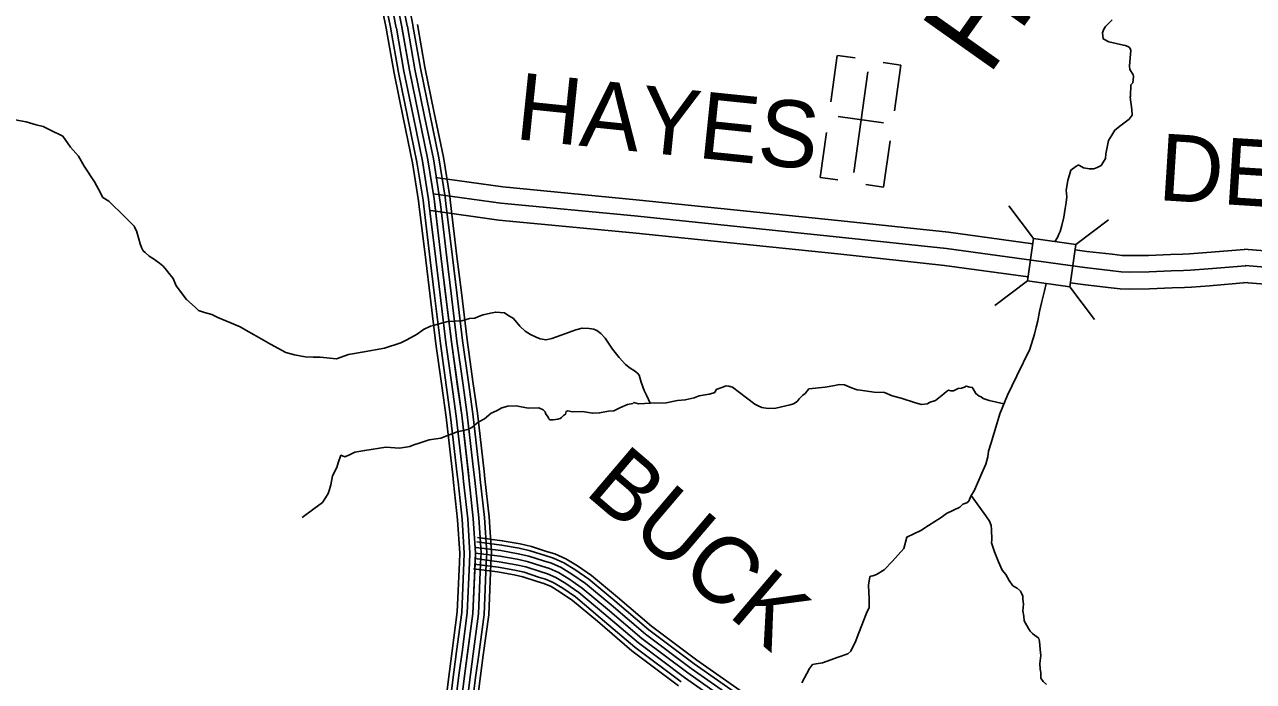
# Model space of a CAD drawing. Extents: x 1551132 to 1791609, y 378168 to 563823.
# Drawn here: x 1664184 to 1670994, y 434729 to 438369 of the extents above; entities that cross this region are included whole.
import ezdxf

# ---------------------------------------------------------------- set-up
doc = ezdxf.new("R2010")
doc.units = 0
for name, color, linetype in [('DESIGN - DRAINAGE - Bridges and Cross Drains Size Text', 7, 'Continuous'), ('DESIGN - ROW - Right-of-Way and Easement Labels', 7, 'Continuous'), ('DESIGN - TRANSPORTATION - Text', 7, 'Continuous'), ('DESIGN - UTILITIES - Cable (Underground) with Text', 7, 'Continuous'), ('SURVEY - CONTOURS - Index with Text', 7, 'Continuous'), ('SURVEY - DRAINAGE - Storm Sewer', 7, 'Continuous'), ('SURVEY - PROPERTY - Owners', 7, 'Continuous'), ('SURVEY - TRANSPORTATION - Roads', 7, 'Continuous')]:
    doc.layers.add(name, color=color, linetype=linetype)

msp = doc.modelspace()

# ---------------------------------------------------------------- linework, layer by layer
at = {"layer": 'DESIGN - TRANSPORTATION - Text'}
for points in [[(1670210.384, 438395.73), (1670174.051, 438357.996), (1670163.893, 438340.054), (1670157.743, 438324.087), (1670161.427, 438289.994), (1670193.259, 438273.677), (1670273.049, 438254.927), (1670285.024, 438252.818), (1670304.94, 438244.618), (1670310.865, 438236.551), (1670314.773, 438226.501), (1670310.381, 438184.475), (1670307.956, 438138.415), (1670309.79, 438120.373), (1670325.539, 438094.181), (1670327.514, 438092.164), (1670329.406, 438080.122), (1670325.089, 438046.113), (1670315.006, 438036.188), (1670312.406, 437972.103), (1670310.356, 437966.111), (1670319.714, 437897.909), (1670321.439, 437867.85), (1670305.24, 437845.958), (1670260.949, 437812.307), (1670226.708, 437784.564), (1670208.458, 437756.689), (1670190.184, 437726.805), (1670175.509, 437652.811), (1670173.268, 437626.794), (1670159.051, 437602.876), (1670150.926, 437588.926), (1670128.827, 437577.109), (1670108.761, 437569.275), (1670084.77, 437569.5), (1670052.845, 437575.801), (1670030.971, 437588.018), (1670026.988, 437590.051), (1670022.988, 437590.093), (1670008.921, 437582.209), (1669982.755, 437562.409), (1669966.222, 437504.465), (1669955.748, 437452.472), (1669959.389, 437414.38), (1669957.089, 437382.345), (1669950.798, 437350.345), (1669942.356, 437302.343), (1669931.931, 437256.367), (1669923.623, 437222.383), (1669915.498, 437208.433), (1669907.315, 437188.474), (1669895.141, 437168.548), (1669894.607, 437167.765)], [(1664111.743, 437845.746), (1664191.558, 437831.171), (1664247.373, 437812.762), (1664287.272, 437804.47), (1664327.08, 437784.17), (1664394.778, 437751.652), (1664438.277, 437689.259), (1664481.876, 437640.883), (1664513.434, 437584.59), (1664570.749, 437498.062), (1664592.432, 437457.853), (1664618.064, 437411.61), (1664649.889, 437391.36), (1664739.162, 437304.616), (1664778.827, 437264.281), (1664790.727, 437252.181), (1664792.702, 437248.164), (1664800.577, 437232.089), (1664804.527, 437226.047), (1664814.235, 437187.929), (1664823.976, 437153.812), (1664831.826, 437133.728), (1664841.684, 437115.636), (1664851.6, 437105.552), (1664873.433, 437085.368), (1664897.299, 437071.185), (1664931.09, 437046.917), (1664948.973, 437032.767), (1664962.839, 437016.65), (1664990.564, 436982.407), (1665006.397, 436962.274), (1665024.088, 436922.089), (1665081.47, 436845.579), (1665129.11, 436803.194), (1665146.96, 436785.044), (1665180.843, 436772.785), (1665220.725, 436762.493), (1665254.574, 436746.235), (1665320.298, 436717.742), (1665378.063, 436693.308), (1665409.895, 436675.058), (1665455.669, 436650.707), (1665547.192, 436597.998), (1665630.774, 436551.346), (1665678.631, 436538.996), (1665738.496, 436528.563), (1665782.437, 436526.254), (1665822.394, 436525.979), (1665912.242, 436517.346), (1665978.349, 436540.921), (1666054.372, 436554.413), (1666178.402, 436575.581), (1666268.525, 436604.998), (1666302.624, 436622.79), (1666358.798, 436654.441), (1666394.947, 436680.225)], [(1669844.442, 436934.05), (1669836.617, 436894.624), (1669820, 436826.664), (1669807.559, 436778.696), (1669799.076, 436726.687), (1669790.768, 436692.711), (1669780.401, 436652.735), (1669755.652, 436570.824), (1669682.312, 436423.245), (1669631.338, 436315.526), (1669588.389, 436211.748), (1669540.932, 436051.91), (1669526.507, 436005.968), (1669522.215, 435973.95), (1669511.849, 435933.982), (1669489.399, 435884.098), (1669448.525, 435788.312), (1669428.234, 435756.444), (1669415.984, 435728.51), (1669405.893, 435718.585), (1669383.835, 435710.768), (1669367.694, 435694.893), (1669293.396, 435659.508)], [(1666394.947, 436680.225), (1666433.046, 436697.992), (1666449.054, 436701.884), (1666473.087, 436709.726), (1666529.136, 436723.36), (1666607.076, 436726.827), (1666649.141, 436740.552), (1666679.124, 436742.344), (1666699.174, 436752.219), (1666725.206, 436760.053), (1666765.239, 436769.786), (1666795.246, 436775.586), (1666843.17, 436771.245), (1666861.061, 436759.103), (1666892.894, 436740.86), (1666928.552, 436698.551), (1666958.317, 436670.3), (1666988.15, 436652.066), (1667018.016, 436637.841), (1667041.924, 436627.666), (1667073.848, 436621.432), (1667105.872, 436629.224), (1667157.963, 436648.883), (1667238.094, 436678.376), (1667274.118, 436686.134), (1667312.076, 436685.868), (1667338.017, 436681.684), (1667355.941, 436673.551), (1667377.799, 436657.375), (1667401.59, 436631.174), (1667441.106, 436570.806), (1667478.73, 436524.48), (1667514.413, 436486.179), (1667540.245, 436465.97), (1667564.103, 436449.786), (1667579.994, 436437.653), (1667589.894, 436425.569), (1667601.611, 436387.435), (1667617.252, 436341.259), (1667631.052, 436315.125), (1667650.593, 436270.79)], [(1669611.305, 436267.124), (1669528.94, 436285.908), (1669497.049, 436296.142), (1669485.133, 436306.242), (1669473.175, 436310.334), (1669455.3, 436324.476), (1669441.501, 436350.61), (1669435.568, 436358.66), (1669421.593, 436360.76), (1669401.643, 436364.91), (1669393.61, 436358.952), (1669375.602, 436355.077), (1669357.603, 436353.193), (1669331.528, 436339.36), (1669317.545, 436339.451), (1669303.587, 436343.56), (1669293.538, 436335.618), (1669277.471, 436323.709), (1669231.239, 436285.975), (1669203.198, 436276.158), (1669185.157, 436268.274), (1669155.157, 436264.474), (1669121.25, 436272.724), (1669041.527, 436299.308), (1668991.67, 436311.675), (1668949.846, 436329.992), (1668891.922, 436332.401), (1668814.074, 436342.951), (1668798.108, 436345.068), (1668766.208, 436355.301), (1668728.384, 436373.593), (1668698.41, 436373.802), (1668674.41, 436369.96), (1668620.395, 436360.326), (1668530.414, 436350.934), (1668510.248, 436325.034), (1668496.19, 436315.117), (1668476.065, 436295.233), (1668465.974, 436281.283), (1668445.891, 436267.399), (1668425.866, 436261.532), (1668347.818, 436244.048), (1668303.844, 436242.348), (1668269.912, 436246.59), (1668250.004, 436256.748), (1668230.087, 436264.89), (1668184.397, 436301.266), (1668106.899, 436359.884), (1668086.966, 436366.035), (1668071, 436368.143), (1668046.95, 436358.301), (1668016.892, 436346.492), (1668008.784, 436330.525), (1667998.768, 436326.592), (1667976.743, 436320.733), (1667922.728, 436311.091), (1667894.687, 436301.274), (1667844.647, 436289.607), (1667802.664, 436285.891), (1667738.632, 436272.315), (1667652.709, 436270.907), (1667586.744, 436267.365), (1667560.828, 436275.557), (1667554.795, 436269.59), (1667524.779, 436263.79), (1667482.697, 436246.056), (1667448.597, 436228.264), (1667420.615, 436226.456), (1667370.591, 436216.789), (1667330.617, 436215.064), (1667274.751, 436225.472), (1667220.794, 436223.839), (1667194.845, 436228.03), (1667184.829, 436224.089), (1667180.729, 436210.097), (1667170.687, 436202.155), (1667158.621, 436192.23), (1667152.588, 436186.263), (1667138.571, 436182.354), (1667112.572, 436178.529), (1667094.589, 436178.654), (1667088.639, 436184.704), (1667082.731, 436196.763), (1667072.848, 436210.847), (1667068.94, 436222.897), (1667057.04, 436234.997), (1667033.132, 436245.173), (1666975.184, 436243.572), (1666907.343, 436256.064), (1666861.378, 436254.381), (1666829.337, 436244.589), (1666799.246, 436228.772), (1666769.18, 436214.963), (1666732.998, 436185.171), (1666696.89, 436165.395), (1666662.707, 436135.586), (1666640.658, 436125.728), (1666580.618, 436112.127), (1666490.445, 436076.701), (1666426.438, 436067.126), (1666370.364, 436049.492)], [(1666370.364, 436049.492), (1666340.323, 436039.683), (1666318.29, 436031.825), (1666262.275, 436022.208), (1666186.385, 436026.741), (1666068.38, 436009.533), (1666014.356, 435999.891), (1665984.273, 435984.082), (1665958.232, 435974.248), (1665936.308, 435982.407), (1665922.016, 435940.447), (1665913.833, 435914.472), (1665889.525, 435868.57), (1665881.167, 435818.561), (1665872.984, 435792.577), (1665866.834, 435770.584), (1665850.676, 435746.667), (1665834.502, 435720.742), (1665786.286, 435685.024), (1665722.004, 435637.398)], [(1669430.401, 435759.844), (1669510.29, 435647.125), (1669532.048, 435616.924), (1669539.865, 435592.84), (1669541.706, 435570.798), (1669543.29, 435514.705), (1669543.165, 435496.679), (1669558.781, 435446.495), (1669580.364, 435392.268), (1669602.005, 435346.05), (1669621.804, 435321.883), (1669639.537, 435287.707), (1669661.312, 435259.515), (1669685.186, 435245.331), (1669703.044, 435229.181), (1669708.969, 435219.13), (1669716.827, 435201.047), (1669716.71, 435185.021), (1669720.502, 435156.962), (1669716.244, 435120.936), (1669722.019, 435090.852), (1669723.827, 435064.801), (1669737.618, 435038.667), (1669747.493, 435022.575), (1669757.384, 435008.492), (1669769.267, 434994.383), (1669783.175, 434984.274), (1669789.142, 434980.232), (1669805.025, 434966.099), (1669808.916, 434952.048), (1669812.575, 434905.956), (1669816.325, 434871.888), (1669810.008, 434827.862), (1669811.783, 434797.811), (1669815.633, 434777.752), (1669815.416, 434747.71), (1669829.274, 434729.593), (1669847.124, 434711.442)], [(1669293.396, 435659.508), (1669263.213, 435637.741), (1669192.815, 435592.307), (1669150.582, 435564.639), (1669072.284, 435529.296), (1669055.701, 435465.336), (1668993.086, 435395.793), (1668946.662, 435348.133), (1668904.438, 435322.474), (1668890.396, 435316.591), (1668884.38, 435314.641), (1668874.364, 435312.724), (1668868.33, 435308.774), (1668859.906, 435262.773), (1668865.197, 435186.604), (1668864.997, 435164.57), (1668864.755, 435138.528), (1668850.464, 435106.602), (1668807.482, 434998.816), (1668786.99, 434944.914), (1668774.807, 434924.989), (1668762.558, 434897.055), (1668746.416, 434881.171), (1668692.276, 434863.637), (1668606.028, 434832.361), (1668569.987, 434826.678), (1668549.963, 434822.853), (1668533.763, 434800.969), (1668491.047, 434721.225)]]:
    msp.add_lwpolyline(points, dxfattribs=at)
at = {"layer": 'DESIGN - UTILITIES - Cable (Underground) with Text'}
for p, q in [((1668687.679, 438198.444), (1668651.216, 437940.405)), ((1668786.09, 438184.695), (1668688.079, 438198.402)), ((1669039.887, 438144.815), (1668941.293, 438159.039)), ((1669004.074, 437890.918), (1669039.804, 438144.882)), ((1668944.049, 437824.132), (1668693.076, 437859.237)), ((1668627.401, 437770.759), (1668592.346, 437521.895)), ((1668944.679, 437468.217), (1668980.601, 437724.064)), ((1668592.446, 437521.979), (1668689.882, 437508.322)), ((1668944.621, 437468.575), (1668846.169, 437482.34))]:
    msp.add_line(p, q, dxfattribs=at)
msp.add_lwpolyline([(1668857.384, 438106.587), (1668778.9, 437549.007)], dxfattribs=at)
at = {"layer": 'SURVEY - CONTOURS - Index with Text'}
for points in [[(1666219.628, 438869.741), (1666231.852, 438846.399), (1666257.418, 438749.754), (1666292.551, 438579.517), (1666335.175, 438368.103), (1666335.766, 438364.786)], [(1666087.881, 438800.764), (1666092.356, 438792.214), (1666112.605, 438715.678), (1666146.837, 438549.791), (1666189.036, 438340.519), (1666189.295, 438339.019)], [(1666109.78, 438812.223), (1666115.538, 438801.214), (1666136.671, 438721.337), (1666171.054, 438554.733), (1666213.327, 438345.102), (1666213.636, 438343.302)], [(1666137.238, 438826.606), (1666144.621, 438812.514), (1666166.862, 438728.445), (1666201.428, 438560.924), (1666243.785, 438350.852), (1666244.168, 438348.677)], [(1666164.704, 438840.982), (1666173.695, 438823.806), (1666197.045, 438735.546), (1666231.802, 438567.125), (1666274.251, 438356.602), (1666274.701, 438354.044)], [(1666192.17, 438855.357), (1666202.77, 438835.098), (1666227.227, 438742.646), (1666262.176, 438573.325), (1666304.717, 438362.353), (1666305.234, 438359.411)], [(1666231.802, 438567.125), (1666274.251, 438356.602), (1666316.475, 438116.046), (1666418.814, 437618.792), (1666453.23, 437404.319), (1666492.779, 437073.686), (1666549.352, 436610.782), (1666606.35, 436203.938), (1666647.666, 435841.253), (1666670.124, 435632.873), (1666682.69, 435440.576), (1666668.198, 435106.301), (1666623.691, 434772.242), (1666581.192, 434438.158)], [(1666189.295, 438339.069), (1666231.285, 438099.804), (1666283.626, 437845.506)], [(1666213.636, 438343.344), (1666255.568, 438104.437), (1666307.833, 437850.489)], [(1666244.168, 438348.702), (1666286.017, 438110.238), (1666338.191, 437856.739)], [(1666274.701, 438354.061), (1666316.475, 438116.046), (1666368.557, 437862.99)], [(1666305.234, 438359.419), (1666346.933, 438121.855), (1666398.923, 437869.24)], [(1666335.766, 438364.778), (1666377.382, 438127.655), (1666429.281, 437875.49)], [(1666361.099, 438369.228), (1666402.648, 438132.472), (1666454.472, 437880.673)], [(1666283.617, 437845.522), (1666333.499, 437603.174), (1666367.332, 437392.294), (1666371.107, 437360.793)], [(1666307.825, 437850.506), (1666357.815, 437607.625), (1666391.814, 437395.719), (1666395.648, 437363.726)], [(1666338.183, 437856.756), (1666388.315, 437613.208), (1666422.522, 437400.019), (1666426.422, 437367.41)], [(1666368.549, 437863.006), (1666418.814, 437618.792), (1666453.23, 437404.319), (1666457.205, 437371.093)], [(1666398.915, 437869.256), (1666449.313, 437624.375), (1666483.937, 437408.619), (1666487.987, 437374.777)], [(1666429.272, 437875.507), (1666479.813, 437629.958), (1666514.645, 437412.92), (1666518.761, 437378.46)], [(1666454.463, 437880.69), (1666505.112, 437634.592), (1666540.111, 437416.486), (1666544.294, 437381.51)], [(1666426.422, 437367.427), (1666462.004, 437069.96), (1666486.32, 436870.939)], [(1666457.205, 437371.11), (1666492.779, 437073.686), (1666517.095, 436874.697)], [(1666487.987, 437374.793), (1666523.553, 437077.411), (1666547.869, 436878.456)], [(1666518.761, 437378.477), (1666554.327, 437081.128), (1666578.635, 436882.214)], [(1666544.294, 437381.527), (1666579.86, 437084.211), (1666604.159, 436885.339)], [(1666371.107, 437360.81), (1666406.689, 437063.277), (1666431.022, 436864.18)], [(1666395.648, 437363.743), (1666431.23, 437066.244), (1666455.554, 436867.18)], [(1666431.022, 436864.197), (1666463.371, 436599.507), (1666495.961, 436366.9)], [(1666455.554, 436867.189), (1666487.878, 436602.715), (1666520.436, 436370.334)], [(1666486.32, 436870.955), (1666518.611, 436606.748), (1666551.135, 436374.634)], [(1666517.095, 436874.714), (1666549.352, 436610.782), (1666581.834, 436378.934)], [(1666547.869, 436878.472), (1666580.093, 436614.815), (1666612.534, 436383.234)], [(1666578.635, 436882.239), (1666610.826, 436618.849), (1666643.233, 436387.534)], [(1666604.159, 436885.356), (1666636.325, 436622.191), (1666668.699, 436391.109)], [(1666495.961, 436366.917), (1666520.319, 436193.013), (1666556.785, 435872.904)], [(1666520.436, 436370.351), (1666544.844, 436196.129), (1666581.343, 435875.704)], [(1666551.135, 436374.651), (1666575.593, 436200.029), (1666612.142, 435879.213)], [(1666581.834, 436378.951), (1666606.35, 436203.938), (1666642.941, 435882.721)], [(1666612.534, 436383.251), (1666637.108, 436207.846), (1666673.74, 435886.23)], [(1666643.233, 436387.551), (1666667.857, 436211.746), (1666704.54, 435889.738)], [(1666668.699, 436391.118), (1666693.373, 436214.988), (1666730.089, 435892.646)], [(1666556.785, 435872.921), (1666561.476, 435831.703), (1666583.709, 435625.398), (1666595.85, 435439.626), (1666593.634, 435388.425)], [(1666581.343, 435875.721), (1666586.042, 435834.42), (1666608.342, 435627.523), (1666620.6, 435439.893), (1666618.325, 435387.35)], [(1666612.142, 435879.229), (1666616.858, 435837.837), (1666639.233, 435630.198), (1666651.649, 435440.235), (1666649.291, 435386.008)], [(1666642.941, 435882.738), (1666647.666, 435841.253), (1666670.124, 435632.873), (1666682.69, 435440.576), (1666680.265, 435384.666)], [(1666673.74, 435886.246), (1666678.474, 435844.67), (1666701.015, 435635.548), (1666713.731, 435440.918), (1666711.239, 435383.325)], [(1666704.54, 435889.755), (1666709.29, 435848.087), (1666731.906, 435638.223), (1666744.78, 435441.26), (1666742.205, 435381.983)], [(1666730.089, 435892.663), (1666734.847, 435850.92), (1666757.53, 435640.44), (1666770.53, 435441.535), (1666767.896, 435380.866)], [(1666593.634, 435388.442), (1666581.734, 435113.918), (1666553.009, 434898.32)], [(1666618.325, 435387.367), (1666606.375, 435111.751), (1666577.509, 434895.062)], [(1666649.291, 435386.025), (1666637.291, 435109.026), (1666608.241, 434890.962)], [(1666680.265, 435384.683), (1666668.198, 435106.301), (1666638.966, 434886.87)], [(1666711.239, 435383.341), (1666699.106, 435103.576), (1666669.69, 434882.778)], [(1666742.205, 435382), (1666730.022, 435100.851), (1666700.423, 434878.678)], [(1666767.896, 435380.883), (1666755.663, 435098.592), (1666725.914, 434875.286)], [(1666553.009, 434898.337), (1666537.701, 434783.442), (1666495.302, 434450.109), (1666488.344, 434404.074)], [(1666577.509, 434895.079), (1666562.209, 434780.251), (1666519.777, 434446.7), (1666512.785, 434400.382)], [(1666608.241, 434890.979), (1666592.95, 434776.242), (1666550.484, 434442.433), (1666543.434, 434395.749)], [(1666638.966, 434886.887), (1666623.691, 434772.242), (1666581.192, 434438.158), (1666574.084, 434391.115)], [(1666669.69, 434882.795), (1666654.432, 434768.242), (1666611.899, 434433.883), (1666604.733, 434386.482)], [(1666700.423, 434878.695), (1666685.173, 434764.234), (1666642.607, 434429.616), (1666635.382, 434381.849)], [(1666725.914, 434875.303), (1666710.672, 434760.917), (1666668.073, 434426.066), (1666660.815, 434378.007)]]:
    msp.add_lwpolyline(points, dxfattribs=at)
at = {"layer": 'SURVEY - DRAINAGE - Storm Sewer'}
for p, q in [((1669774.904, 437183.768), (1669638.208, 437365.156)), ((1670010.197, 437150.707), (1670191.586, 437287.387)), ((1669741.843, 436948.466), (1669560.463, 436811.787)), ((1669977.086, 436915.414), (1670113.783, 436734.034))]:
    msp.add_line(p, q, dxfattribs=at)
msp.add_lwpolyline([(1669741.843, 436948.466), (1669977.136, 436915.414), (1670010.197, 437150.707), (1669774.904, 437183.768)], close=True, dxfattribs=at)
at = {"layer": 'SURVEY - PROPERTY - Owners'}
for points in [[(1666461.321, 437521.881), (1666833.312, 437469.938), (1667572.645, 437398.928), (1668709.485, 437281.859), (1669304.129, 437217.949), (1669770.685, 437153.764)], [(1666448.78, 437432.045), (1666822.696, 437379.827), (1667563.662, 437308.659), (1668699.994, 437191.648), (1669293.096, 437127.905), (1670059.712, 437022.444), (1670200.867, 437006.019), (1670261.382, 436998.486), (1670309.356, 436998.027), (1670415.32, 436999.019), (1670538.717, 437004.053), (1670607.307, 437007.194), (1670645.306, 437008.836), (1670742.996, 437015.845), (1670951.441, 437033.153)], [(1666435.738, 437338.659), (1666811.663, 437286.158), (1667554.329, 437214.832), (1668690.127, 437097.871), (1669281.63, 437034.303), (1669744.961, 436970.56)], [(1670006.08, 437121.389), (1670071.136, 437112.438), (1670211.708, 437096.08), (1670267.44, 437089.146), (1670309.364, 437088.738), (1670413.045, 437089.713), (1670534.792, 437094.68), (1670603.274, 437097.813), (1670640.106, 437099.405), (1670735.996, 437106.289), (1670943.933, 437123.556)], [(1670942.083, 437124.881), (1671354.406, 437092.205), (1671650.433, 437073.472), (1671800.129, 437059.421), (1671835.953, 437050.629), (1671899.177, 437041.871), (1671915.085, 437037.437)], [(1670948.857, 437033.362), (1671347.956, 437001.72)], [(1669980.33, 436938.176), (1670047.837, 436928.892), (1670189.592, 436912.4), (1670255.09, 436904.25), (1670309.347, 436903.725), (1670417.686, 436904.742), (1670542.792, 436909.85), (1670611.499, 436912.992), (1670650.714, 436914.684), (1670750.27, 436921.834), (1670959.24, 436939.184)], [(1670941.408, 436939.359), (1671341.256, 436907.659), (1671635.95, 436889.008), (1671769.263, 436876.5), (1671801.112, 436868.683), (1671861.494, 436860.316), (1671875.527, 436856.408)]]:
    msp.add_lwpolyline(points, dxfattribs=at)
at = {"layer": 'SURVEY - TRANSPORTATION - Roads'}
for points in [[(1666693.698, 435526.595), (1666830.612, 435509.07), (1666930.409, 435491.419), (1666992.283, 435477.519), (1667076.747, 435449.793), (1667123.088, 435436.06), (1667182.828, 435409.034), (1667247.152, 435370.425), (1667326.15, 435315.832), (1667470.296, 435195.537), (1667658.909, 435034.958), (1667909.711, 434846.695), (1668167.088, 434665.882)], [(1666686.623, 435471.327), (1666822.22, 435453.977), (1666919.443, 435436.776), (1666977.45, 435423.743), (1667060.139, 435396.6), (1667103.597, 435383.717), (1667156.929, 435359.599), (1667216.952, 435323.565), (1667292.401, 435271.43), (1667434.389, 435152.927), (1667624.093, 434991.423), (1667876.962, 434801.602), (1668136.089, 434619.564)], [(1666690.556, 435502.078), (1666826.895, 435484.628), (1666925.543, 435467.185), (1666985.7, 435453.668), (1667069.381, 435426.201), (1667114.447, 435412.842), (1667171.337, 435387.1), (1667233.752, 435349.641), (1667311.175, 435296.139), (1667454.363, 435176.636), (1667643.467, 435015.641), (1667895.186, 434826.694), (1668153.33, 434645.331)], [(1666678.757, 435409.825), (1666812.887, 435392.658), (1666907.243, 435375.975), (1666960.95, 435363.908), (1667041.657, 435337.415), (1667081.914, 435325.482), (1667128.096, 435304.581), (1667183.336, 435271.43), (1667254.835, 435222.029), (1667394.423, 435105.526), (1667585.36, 434942.972), (1667840.529, 434751.434), (1668101.59, 434568.029)], [(1666682.69, 435440.576), (1666817.553, 435423.318), (1666913.343, 435406.376), (1666969.2, 435393.825), (1667050.898, 435367.008), (1667092.755, 435354.599), (1667142.512, 435332.09), (1667200.144, 435297.498), (1667273.618, 435246.73), (1667414.406, 435129.227), (1667604.726, 434967.198), (1667858.745, 434776.518), (1668118.839, 434593.797)], [(1666682.69, 435440.576), (1666817.553, 435423.318), (1666913.343, 435406.376), (1666969.2, 435393.825), (1667050.898, 435367.008), (1667092.755, 435354.599), (1667142.512, 435332.09), (1667200.144, 435297.498), (1667273.618, 435246.73), (1667414.406, 435129.227), (1667604.726, 434967.198), (1667858.745, 434776.518), (1668118.839, 434593.797)], [(1666671.557, 435353.566), (1666804.337, 435336.574), (1666896.085, 435320.348), (1666945.85, 435309.165), (1667024.749, 435283.264), (1667062.073, 435272.205), (1667101.73, 435254.263), (1667152.596, 435223.729), (1667220.477, 435176.828), (1667357.874, 435062.158), (1667549.919, 434898.663), (1667807.197, 434705.533)], [(1666674.823, 435379.075), (1666808.212, 435362.008), (1666901.143, 435345.566), (1666952.7, 435333.982), (1667032.415, 435307.815), (1667071.064, 435296.356), (1667113.688, 435277.081), (1667166.537, 435245.355), (1667236.06, 435197.32), (1667374.449, 435081.817), (1667565.986, 434918.755), (1667822.305, 434726.341)]]:
    msp.add_lwpolyline(points, dxfattribs=at)

# ---------------------------------------------------------------- texts
at = {"layer": 'DESIGN - DRAINAGE - Bridges and Cross Drains Size Text'}
msp.add_text('Hurricane', height=475.0048, rotation=54.7330083, dxfattribs=at).set_placement((1669524.466, 438078.588))
at = {"layer": 'DESIGN - ROW - Right-of-Way and Easement Labels'}
for s, height, rotation, p in [('HAYES', 369.9915, 354.1205361, (1666896.186, 437735.636)), ('DENTON', 369.9914, 356.3789333, (1670460.919, 437397.154)), ('BUCK', 369.9989, 319.5898583, (1667280.884, 435773.119))]:
    msp.add_text(s, height=height, rotation=rotation, dxfattribs=at).set_placement(p)

doc.saveas('drawing.dxf')
